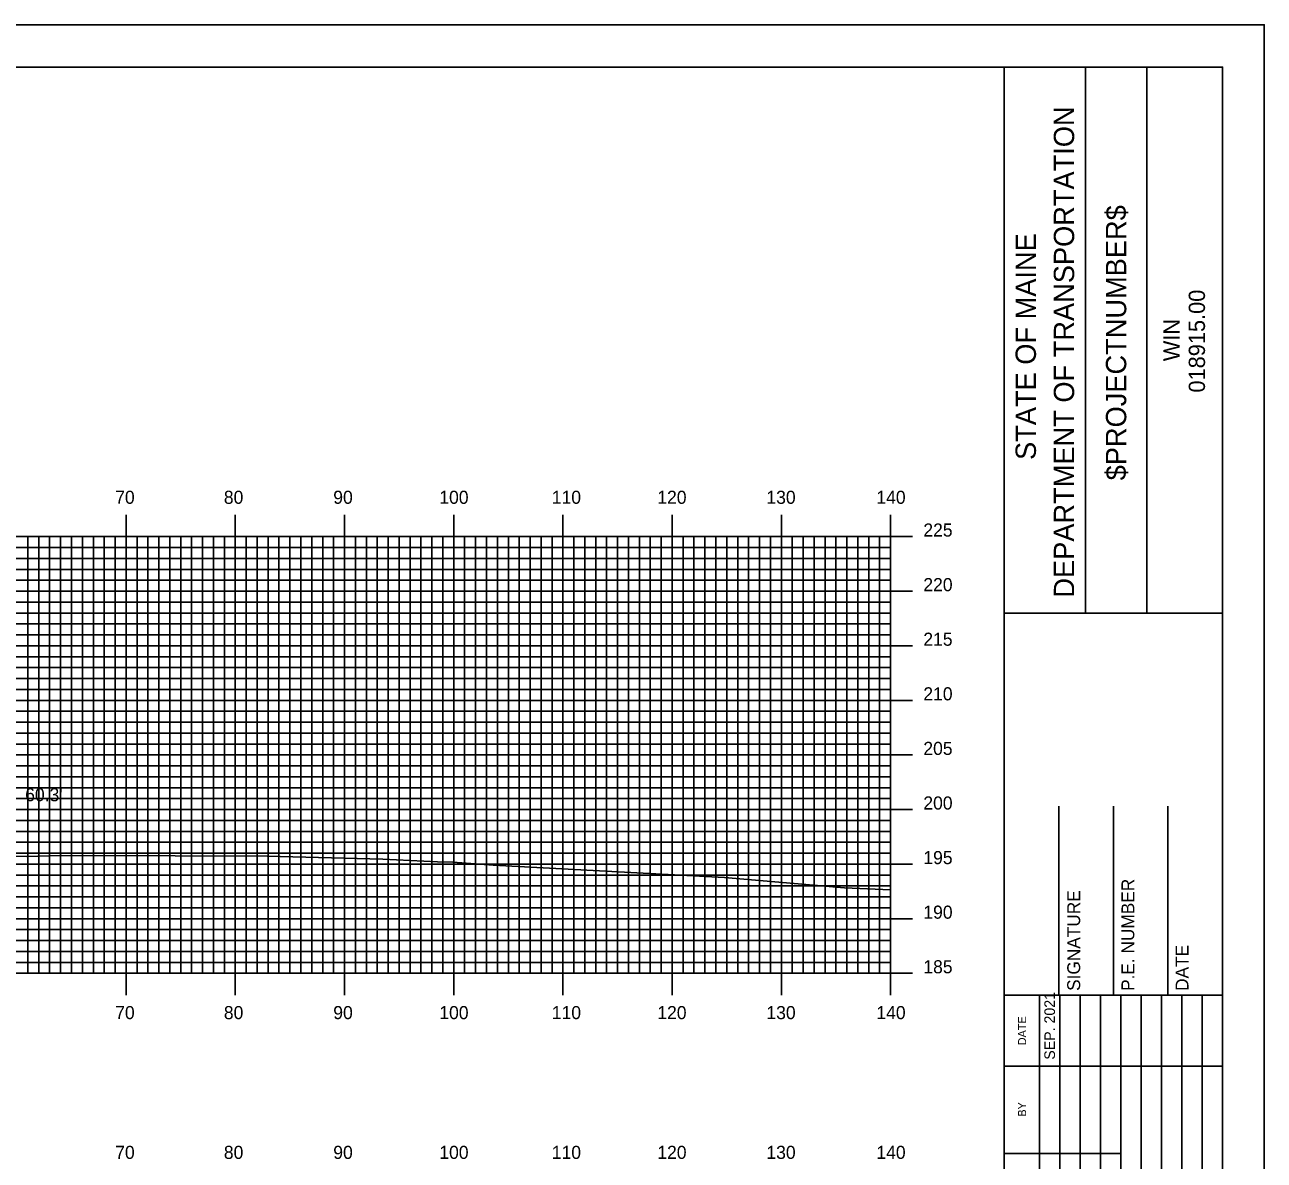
# Model space of a CAD drawing. Extents: x 1812161 to 1812504, y 442591 to 442811.
# Drawn here: x 1812387.2 to 1812500.6, y 442706.6 to 442810.5 of the extents above; entities that cross this region are included whole.
import ezdxf

# ---------------------------------------------------------------- set-up
doc = ezdxf.new("R2010")
doc.units = 0
for name, color, linetype in [('BORDER', 7, 'Continuous'), ('D_Text_Standard', 7, 'Continuous'), ('H_V ANNOTATION', 7, 'Continuous'), ('MAJOR', 7, 'Continuous'), ('MINOR', 7, 'Continuous'), ('PLOT BOUNDARY', 7, 'Continuous'), ('S_Roadway_Centerline', 7, 'Continuous')]:
    doc.layers.add(name, color=color, linetype=linetype)

msp = doc.modelspace()

# ---------------------------------------------------------------- linework, layer by layer
at = {"layer": 'BORDER'}
for p, q in [((1812476.83, 442596.67), (1812476.83, 442806.67)), ((1812484.29, 442756.66), (1812484.29, 442806.66)), ((1812489.88, 442756.66), (1812489.88, 442806.66)), ((1812476.83, 442756.65), (1812496.83, 442756.65)), ((1812481.83, 442721.67), (1812481.83, 442738.97)), ((1812486.83, 442721.67), (1812486.83, 442738.97)), ((1812491.83, 442721.67), (1812491.83, 442738.97)), ((1812476.83, 442721.67), (1812496.83, 442721.67))]:
    msp.add_line(p, q, dxfattribs=at)
msp.add_lwpolyline([(1812176.83, 442596.67), (1812496.83, 442596.67), (1812496.83, 442806.67), (1812176.83, 442806.67)], close=True, dxfattribs=at)
for points in [[(1812480.06, 442715.17), (1812480.06, 442721.67)], [(1812481.92, 442686.68), (1812481.92, 442721.67)], [(1812483.79, 442721.67), (1812483.79, 442686.68)], [(1812485.65, 442686.68), (1812485.65, 442721.67)], [(1812487.51, 442686.68), (1812487.51, 442721.67)], [(1812489.38, 442686.68), (1812489.38, 442721.67)], [(1812491.24, 442686.68), (1812491.24, 442721.67)], [(1812493.1, 442686.68), (1812493.1, 442721.67)], [(1812494.97, 442686.68), (1812494.97, 442721.67)], [(1812480.06, 442686.68), (1812480.06, 442720.26)], [(1812476.83, 442715.17), (1812496.83, 442715.17)], [(1812476.83, 442707.17), (1812480.06, 442707.17)], [(1812480.06, 442707.17), (1812487.51, 442707.17)]]:
    msp.add_lwpolyline(points, dxfattribs=at)
at = {"layer": 'MAJOR'}
for p, q in [((1812396.43, 442765.67), (1812396.43, 442763.67)), ((1812406.43, 442765.67), (1812406.43, 442763.67)), ((1812416.43, 442765.67), (1812416.43, 442763.67)), ((1812426.43, 442765.67), (1812426.43, 442763.67)), ((1812436.43, 442765.67), (1812436.43, 442763.67)), ((1812446.43, 442765.67), (1812446.43, 442763.67)), ((1812456.43, 442765.67), (1812456.43, 442763.67)), ((1812466.43, 442765.67), (1812466.43, 442763.67)), ((1812186.43, 442763.67), (1812466.43, 442763.67)), ((1812186.43, 442763.67), (1812466.43, 442763.67)), ((1812396.43, 442723.67), (1812396.43, 442763.67)), ((1812406.43, 442723.67), (1812406.43, 442763.67)), ((1812416.43, 442723.67), (1812416.43, 442763.67)), ((1812426.43, 442723.67), (1812426.43, 442763.67)), ((1812436.43, 442723.67), (1812436.43, 442763.67)), ((1812446.43, 442723.67), (1812446.43, 442763.67)), ((1812456.43, 442723.67), (1812456.43, 442763.67)), ((1812468.43, 442763.67), (1812464.42, 442763.67)), ((1812466.43, 442723.67), (1812466.43, 442763.67)), ((1812466.43, 442723.67), (1812466.43, 442763.67)), ((1812186.43, 442758.67), (1812466.43, 442758.67)), ((1812468.43, 442758.67), (1812464.42, 442758.67)), ((1812186.43, 442753.67), (1812466.43, 442753.67)), ((1812468.43, 442753.67), (1812464.42, 442753.67)), ((1812186.43, 442748.67), (1812466.43, 442748.67)), ((1812468.43, 442748.67), (1812464.42, 442748.67)), ((1812186.43, 442743.67), (1812466.43, 442743.67)), ((1812468.43, 442743.67), (1812464.42, 442743.67)), ((1812186.43, 442738.67), (1812466.43, 442738.67)), ((1812468.43, 442738.67), (1812464.42, 442738.67)), ((1812186.43, 442733.67), (1812466.43, 442733.67)), ((1812468.43, 442733.67), (1812464.42, 442733.67)), ((1812186.43, 442728.67), (1812466.43, 442728.67)), ((1812468.43, 442728.67), (1812464.42, 442728.67)), ((1812186.43, 442723.67), (1812466.43, 442723.67)), ((1812186.43, 442723.67), (1812466.43, 442723.67)), ((1812396.43, 442721.66), (1812396.43, 442723.67)), ((1812406.43, 442721.66), (1812406.43, 442723.67)), ((1812416.43, 442721.66), (1812416.43, 442723.67)), ((1812426.43, 442721.66), (1812426.43, 442723.67)), ((1812436.43, 442721.66), (1812436.43, 442723.67)), ((1812446.43, 442721.66), (1812446.43, 442723.67)), ((1812456.43, 442721.66), (1812456.43, 442723.67)), ((1812468.43, 442723.67), (1812464.42, 442723.67)), ((1812466.43, 442721.66), (1812466.43, 442723.67))]:
    msp.add_line(p, q, dxfattribs=at)
at = {"layer": 'MINOR'}
for p, q in [((1812387.43, 442723.67), (1812387.43, 442763.67)), ((1812388.43, 442723.67), (1812388.43, 442763.67)), ((1812389.43, 442723.67), (1812389.43, 442763.67)), ((1812390.43, 442723.67), (1812390.43, 442763.67)), ((1812391.43, 442723.67), (1812391.43, 442763.67)), ((1812392.43, 442723.67), (1812392.43, 442763.67)), ((1812393.43, 442723.67), (1812393.43, 442763.67)), ((1812394.43, 442723.67), (1812394.43, 442763.67)), ((1812395.43, 442723.67), (1812395.43, 442763.67)), ((1812397.43, 442723.67), (1812397.43, 442763.67)), ((1812398.43, 442723.67), (1812398.43, 442763.67)), ((1812399.43, 442723.67), (1812399.43, 442763.67)), ((1812400.43, 442723.67), (1812400.43, 442763.67)), ((1812401.43, 442723.67), (1812401.43, 442763.67)), ((1812402.43, 442723.67), (1812402.43, 442763.67)), ((1812403.43, 442723.67), (1812403.43, 442763.67)), ((1812404.43, 442723.67), (1812404.43, 442763.67)), ((1812405.43, 442723.67), (1812405.43, 442763.67)), ((1812407.43, 442723.67), (1812407.43, 442763.67)), ((1812408.43, 442723.67), (1812408.43, 442763.67)), ((1812409.43, 442723.67), (1812409.43, 442763.67)), ((1812410.43, 442723.67), (1812410.43, 442763.67)), ((1812411.43, 442723.67), (1812411.43, 442763.67)), ((1812412.43, 442723.67), (1812412.43, 442763.67)), ((1812413.43, 442723.67), (1812413.43, 442763.67)), ((1812414.43, 442723.67), (1812414.43, 442763.67)), ((1812415.43, 442723.67), (1812415.43, 442763.67)), ((1812417.43, 442723.67), (1812417.43, 442763.67)), ((1812418.43, 442723.67), (1812418.43, 442763.67)), ((1812419.43, 442723.67), (1812419.43, 442763.67)), ((1812420.43, 442723.67), (1812420.43, 442763.67)), ((1812421.43, 442723.67), (1812421.43, 442763.67)), ((1812422.43, 442723.67), (1812422.43, 442763.67)), ((1812423.43, 442723.67), (1812423.43, 442763.67)), ((1812424.43, 442723.67), (1812424.43, 442763.67)), ((1812425.43, 442723.67), (1812425.43, 442763.67)), ((1812427.43, 442723.67), (1812427.43, 442763.67)), ((1812428.43, 442723.67), (1812428.43, 442763.67)), ((1812429.43, 442723.67), (1812429.43, 442763.67)), ((1812430.43, 442723.67), (1812430.43, 442763.67)), ((1812431.43, 442723.67), (1812431.43, 442763.67)), ((1812432.43, 442723.67), (1812432.43, 442763.67)), ((1812433.43, 442723.67), (1812433.43, 442763.67)), ((1812434.43, 442723.67), (1812434.43, 442763.67)), ((1812435.43, 442723.67), (1812435.43, 442763.67)), ((1812437.43, 442723.67), (1812437.43, 442763.67)), ((1812438.43, 442723.67), (1812438.43, 442763.67)), ((1812439.43, 442723.67), (1812439.43, 442763.67)), ((1812440.43, 442723.67), (1812440.43, 442763.67)), ((1812441.43, 442723.67), (1812441.43, 442763.67)), ((1812442.43, 442723.67), (1812442.43, 442763.67)), ((1812443.43, 442723.67), (1812443.43, 442763.67)), ((1812444.43, 442723.67), (1812444.43, 442763.67)), ((1812445.43, 442723.67), (1812445.43, 442763.67)), ((1812447.43, 442723.67), (1812447.43, 442763.67)), ((1812448.43, 442723.67), (1812448.43, 442763.67)), ((1812449.43, 442723.67), (1812449.43, 442763.67)), ((1812450.43, 442723.67), (1812450.43, 442763.67)), ((1812451.43, 442723.67), (1812451.43, 442763.67)), ((1812452.43, 442723.67), (1812452.43, 442763.67)), ((1812453.43, 442723.67), (1812453.43, 442763.67)), ((1812454.43, 442723.67), (1812454.43, 442763.67)), ((1812455.43, 442723.67), (1812455.43, 442763.67)), ((1812457.43, 442723.67), (1812457.43, 442763.67)), ((1812458.43, 442723.67), (1812458.43, 442763.67)), ((1812459.43, 442723.67), (1812459.43, 442763.67)), ((1812460.43, 442723.67), (1812460.43, 442763.67)), ((1812461.43, 442723.67), (1812461.43, 442763.67)), ((1812462.43, 442723.67), (1812462.43, 442763.67)), ((1812463.43, 442723.67), (1812463.43, 442763.67)), ((1812464.43, 442723.67), (1812464.43, 442763.67)), ((1812465.43, 442723.67), (1812465.43, 442763.67)), ((1812186.43, 442762.67), (1812466.43, 442762.67)), ((1812466.43, 442762.67), (1812464.42, 442762.67)), ((1812186.43, 442761.67), (1812466.43, 442761.67)), ((1812466.43, 442761.67), (1812464.42, 442761.67)), ((1812186.43, 442760.67), (1812466.43, 442760.67)), ((1812466.43, 442760.67), (1812464.42, 442760.67)), ((1812186.43, 442759.67), (1812466.43, 442759.67)), ((1812466.43, 442759.67), (1812464.42, 442759.67)), ((1812186.43, 442757.67), (1812466.43, 442757.67)), ((1812466.43, 442757.67), (1812464.42, 442757.67)), ((1812186.43, 442756.67), (1812466.43, 442756.67)), ((1812466.43, 442756.67), (1812464.42, 442756.67)), ((1812186.43, 442755.67), (1812466.43, 442755.67)), ((1812186.43, 442754.67), (1812466.43, 442754.67)), ((1812466.43, 442755.67), (1812464.42, 442755.67)), ((1812466.43, 442754.67), (1812464.42, 442754.67)), ((1812186.43, 442752.67), (1812466.43, 442752.67)), ((1812466.43, 442752.67), (1812464.42, 442752.67)), ((1812186.43, 442751.67), (1812466.43, 442751.67)), ((1812466.43, 442751.67), (1812464.42, 442751.67)), ((1812186.43, 442750.67), (1812466.43, 442750.67)), ((1812466.43, 442750.67), (1812464.42, 442750.67)), ((1812186.43, 442749.67), (1812466.43, 442749.67)), ((1812466.43, 442749.67), (1812464.42, 442749.67)), ((1812186.43, 442747.67), (1812466.43, 442747.67)), ((1812186.43, 442746.67), (1812466.43, 442746.67)), ((1812466.43, 442747.67), (1812464.42, 442747.67)), ((1812466.43, 442746.67), (1812464.42, 442746.67)), ((1812186.43, 442745.67), (1812466.43, 442745.67)), ((1812466.43, 442745.67), (1812464.42, 442745.67)), ((1812186.43, 442744.67), (1812466.43, 442744.67)), ((1812466.43, 442744.67), (1812464.42, 442744.67)), ((1812186.43, 442742.67), (1812466.43, 442742.67)), ((1812466.43, 442742.67), (1812464.42, 442742.67)), ((1812186.43, 442741.67), (1812466.43, 442741.67)), ((1812466.43, 442741.67), (1812464.42, 442741.67)), ((1812186.43, 442740.67), (1812466.43, 442740.67)), ((1812466.43, 442740.67), (1812464.42, 442740.67)), ((1812186.43, 442739.67), (1812466.43, 442739.67)), ((1812466.43, 442739.67), (1812464.42, 442739.67)), ((1812186.43, 442737.67), (1812466.43, 442737.67)), ((1812466.43, 442737.67), (1812464.42, 442737.67)), ((1812186.43, 442736.67), (1812466.43, 442736.67)), ((1812466.43, 442736.67), (1812464.42, 442736.67)), ((1812186.43, 442735.67), (1812466.43, 442735.67)), ((1812466.43, 442735.67), (1812464.42, 442735.67)), ((1812186.43, 442734.67), (1812466.43, 442734.67)), ((1812466.43, 442734.67), (1812464.42, 442734.67)), ((1812186.43, 442732.67), (1812466.43, 442732.67)), ((1812466.43, 442732.67), (1812464.42, 442732.67)), ((1812186.43, 442731.67), (1812466.43, 442731.67)), ((1812466.43, 442731.67), (1812464.42, 442731.67)), ((1812186.43, 442730.67), (1812466.43, 442730.67)), ((1812186.43, 442729.67), (1812466.43, 442729.67)), ((1812466.43, 442730.67), (1812464.42, 442730.67)), ((1812466.43, 442729.67), (1812464.42, 442729.67)), ((1812186.43, 442727.67), (1812466.43, 442727.67)), ((1812466.43, 442727.67), (1812464.42, 442727.67)), ((1812186.43, 442726.67), (1812466.43, 442726.67)), ((1812466.43, 442726.67), (1812464.42, 442726.67)), ((1812186.43, 442725.67), (1812466.43, 442725.67)), ((1812466.43, 442725.67), (1812464.42, 442725.67)), ((1812186.43, 442724.67), (1812466.43, 442724.67)), ((1812466.43, 442724.67), (1812464.42, 442724.67))]:
    msp.add_line(p, q, dxfattribs=at)
at = {"layer": 'PLOT BOUNDARY'}
msp.add_lwpolyline([(1812160.64, 442590.55), (1812500.64, 442590.55), (1812500.64, 442810.55), (1812160.64, 442810.55)], close=True, dxfattribs=at)
at = {"layer": 'S_Roadway_Centerline'}
msp.add_lwpolyline([(1812377.85, 442734.45), (1812387.27, 442734.36), (1812390.51, 442734.46), (1812400.91, 442734.44), (1812409.35, 442734.41), (1812419.95, 442734.13), (1812424.93, 442733.89), (1812426.35, 442733.84), (1812430.04, 442733.56), (1812451.21, 442732.44), (1812462.2, 442731.5), (1812466.43, 442731.32)], dxfattribs=at)

# ---------------------------------------------------------------- texts
at = {"layer": 'BORDER'}
for s, height, p in [('DEPARTMENT OF TRANSPORTATION', 1.8635, (1812483.24, 442758.08)), ('$PROJECTNUMBER$', 1.8635, (1812488.01, 442768.82)), ('STATE OF MAINE', 1.8635, (1812479.74, 442770.69)), ('018915.00', 1.491, (1812495.22, 442776.86)), ('WIN', 1.491, (1812492.9, 442779.73)), ('P.E. NUMBER', 1.1811, (1812488.75, 442722.06)), ('SIGNATURE', 1.181, (1812483.79, 442722.06)), ('DATE', 1.181, (1812493.71, 442722.06)), ('SEP. 2021', 0.969, (1812481.48, 442715.76)), ('DATE', 0.743, (1812478.84, 442717.08)), ('BY', 0.743, (1812478.84, 442710.54))]:
    msp.add_text(s, height=height, rotation=90, dxfattribs=at).set_placement(p)
at = {"layer": 'D_Text_Standard'}
msp.add_text("60.3'", height=1.2, dxfattribs=at).set_placement((1812387.19, 442739.43))
at = {"layer": 'H_V ANNOTATION'}
for s, p in [('70', (1812395.43, 442766.67)), ('80', (1812405.38, 442766.67)), ('90', (1812415.4, 442766.67)), ('100', (1812425.11, 442766.67)), ('110', (1812435.41, 442766.67)), ('120', (1812445.07, 442766.67)), ('130', (1812455.06, 442766.67)), ('140', (1812465.13, 442766.67)), ('225', (1812469.43, 442763.67)), ('220', (1812469.43, 442758.67)), ('215', (1812469.43, 442753.67)), ('210', (1812469.43, 442748.67)), ('205', (1812469.43, 442743.67)), ('200', (1812469.43, 442738.67)), ('195', (1812469.43, 442733.67)), ('190', (1812469.43, 442728.67)), ('185', (1812469.43, 442723.67)), ('70', (1812395.43, 442719.47)), ('80', (1812405.38, 442719.47)), ('90', (1812415.4, 442719.47)), ('100', (1812425.11, 442719.47)), ('110', (1812435.41, 442719.47)), ('120', (1812445.07, 442719.47)), ('130', (1812455.06, 442719.47)), ('140', (1812465.13, 442719.47)), ('70', (1812395.43, 442706.67)), ('80', (1812405.38, 442706.67)), ('90', (1812415.4, 442706.67)), ('100', (1812425.11, 442706.67)), ('110', (1812435.41, 442706.67)), ('120', (1812445.07, 442706.67)), ('130', (1812455.06, 442706.67)), ('140', (1812465.13, 442706.67))]:
    msp.add_text(s, height=1.2, dxfattribs=at).set_placement(p)

doc.saveas('drawing.dxf')
